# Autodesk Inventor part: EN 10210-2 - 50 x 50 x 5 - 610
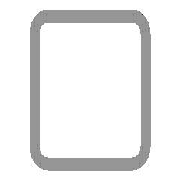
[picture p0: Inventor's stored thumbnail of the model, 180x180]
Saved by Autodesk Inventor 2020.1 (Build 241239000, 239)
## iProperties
IsCustomPart: 1
_CCFamilyMember: 16
_CCFamilyDisplayName: DIN EN 10210-2 (USAS B17.1 quadratisch) - Rohrleitung — In Klammern angegebene Größen wurden aufgehoben
_FrameMemberDoc: Frame Member File
_Version: 15.0.0
_GetPNFromCC: 1
Created: 2019-01
Part Number: EN 10210-2 - 50 x 50 x 5 - 610
Material: Stahl, weich
Description: Rohrleitung
Document SubType Name: Modeling
Standard: DIN
Designer: lutzd
Standard Revision: 2006-07
Standards Organization: DIN
Language: de-DE
Size Designation: 50 x 50 x 5
Categories: <MemberInstance><Categories><Category DisplayName="Profile" InternalName="089c4875-fa83-4c05-b084-43b9cc11f5ed" Mnemonic="GRDR"><CategoryParameter DisplayName="
Stock Number: 50 x 50 x 5
Mass: 4175.75 g
Surface Area: 2083.96 cm^2
Volume: 531.943 cm^3
Density: 7.85 g/cm^3
Appearance: Halbpoliert
G_L: 610,000 mm
G_W: 50,000 mm
G_H: 50,000 mm
DocNumber: ADSK-014143
Folder: .
Dimensions: 50x50x610 mm
Mass: 4,176 kg
+09049A96-A2C2-4B31-98A1-8556EA1320A1+SCHNITTDETAIL1: Schnittwinkel 90,00 grd
Title: Profil-Bauteil
Author: lutzd
Revision Number: -
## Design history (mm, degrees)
node "Startebene"
node "Endebene"
sketch "Skizze"
  geometry: L1 (-25, -17.5)-(-25, 17.5); L2 (-17.5, 25)-(17.5, 25); L3 (25, 17.5)-(25, -17.5); L4 (17.5, -25)-(-17.5, -25); L5 (-15, 20)-(15, 20); L6 (20, 15)-(20, -15); L7 (15, -20)-(-15, -20); L8 (-20, -15)-(-20, 15); L9 (0, 37.175)-(0, -37.175) reference; L10 (-37.175, 0)-(37.175, 0) reference; A1 r 7.5 centre (-17.5, -17.5) between (-25, -17.5) and (-17.5, -25); A2 r 7.5 centre (-17.5, 17.5) between (-17.5, 25) and (-25, 17.5); A3 r 7.5 centre (17.5, 17.5) between (25, 17.5) and (17.5, 25); A4 r 7.5 centre (17.5, -17.5) between (17.5, -25) and (25, -17.5); A5 r 5 centre (-15, -15) between (-20, -15) and (-15, -20); A6 r 5 centre (-15, 15) between (-15, 20) and (-20, 15); A7 r 5 centre (15, 15) between (20, 15) and (15, 20); A8 r 5 centre (15, -15) between (15, -20) and (20, -15)
  constraints: 16 end point, 16 point on circle, 16 tangent, 8 centre point, 6 equal radius, 4 parallel, 2 perpendicular, 2 other
  dimensions: "d7" = 7.5 radius of A1 (= G_IR); "d10" = 50 distance between parallel lines of L2 L4 (= G_H); "d11" = 50 distance between parallel lines of L1 L3 (= G_W); "d12" = 5 distance between parallel lines of L3 L6 (= G_T); "d15" = 25 distance between parallel lines of L2 L10 (= 0.5 x d10); "d16" = 25 distance between parallel lines of L9 L3 (= 0.5 x d11); "d19" = 5 radius of A5 (= G_T); "d20" = 5 distance between parallel lines of L4 L7 (= G_T)
extrude "Körper" new body sketch "Skizze" stored distance "d3" = 610 (= G_L); taper "d4" = 0 deg
node "Driven Length"
  sketch "Sketch3"
    geometry: L1 (0, 0)-(10, 0) reference
    constraints: 2 end point, 1 horizontal
  workplane "Work Plane3"
  sketch "Sketch4"
    geometry: L1 (-2, 25)-(12, 25) reference; L2 (-2, 635)-(12, 635) reference
    dimensions: "d18" = 610 distance between parallel lines of L1 L2 (derived)
workplane "Arbeitsebene4"
feature "Trennen1"
sketch "Skizze5"
  geometry: L1 (-35, 610)-(0, 610) reference; L2 (-17.5, 610)-(-17.5, 181.937); 3 further points
  constraints: 2 end point, 2 point on line, 1 midpoint, 1 vertical
  dimensions: "d21" = 45 distance of point (-17.5, 225) point (-17.5, 180); "d22" = 385 distance from line of point (-17.5, 225) L1
hole "Bohrung1" sketch "Skizze5" at (-17.5, 180), (-17.5, 225) diameter "d23" = 6.647; stored, may be unused: countersink angle "d27" = 90 deg, drill point angle "d29" = 118 deg; dims "d24" = 16, "d25" = 4, "d26" = 2, "d28" = 8
sketch "Skizze6"
  geometry: L1 (610, 35)-(610, 0) reference; L2 (610, 17.5)-(289, 17.5); 3 further points
  constraints: 2 end point, 1 coincident, 1 horizontal, 1 midpoint, 1 point on line
  dimensions: "d30" = 41 distance of point (330, 17.5) point (289, 17.5); "d31" = 280 distance from line of L1 point (330, 17.5)
hole "Bohrung2" sketch "Skizze6" at (289, 17.5), (330, 17.5) diameter "d32" = 6.647; stored, may be unused: countersink angle "d36" = 90 deg, drill point angle "d38" = 118 deg; dims "d33" = 16, "d34" = 4, "d35" = 2, "d37" = 8
body "Solid1"
other parameters: "G_W" = 50 [user parameter; used in 1 equation term], "G_H" = 50 [user parameter; used in 1 equation term], "G_T" = 5 [user parameter; used in 3 equation terms], "G_IR" = 7.5 [user parameter; used in 1 equation term], "G_L" = 610 (= d18) [user parameter; used in 1 equation term], "G_OFFSET_START" = -25 [user parameter; used in 1 equation term], "G_OFFSET_END" = 0 [user parameter; used in 1 equation term], "d13" = 25 (= -G_OFFSET_START), "d14" = 635 (= G_OFFSET_END + B_L), "B_L" = 635 [user parameter; used in 1 equation term], "d17" = 90 deg
